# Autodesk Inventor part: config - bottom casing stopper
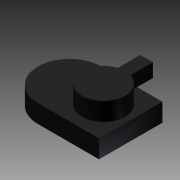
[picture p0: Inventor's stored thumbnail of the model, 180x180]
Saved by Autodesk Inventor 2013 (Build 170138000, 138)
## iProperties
Company: Autodesk Inc.
Created: 2005-12
Part Number: config - bottom casing stopper
Document SubType Name: Modeling
Designer: Autodesk Inc.
Stock Number: config - bottom casing stopper
Density: 1 g/cm^3
Mass: 1.3879 g
Surface Area: 9.59913 cm^2
Volume: 1.3879 cm^3
Material: Allgemein
Title: PC Demo
Author: Autodesk Inc.
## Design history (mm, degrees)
sketch "Sketch1"
  geometry: L1 (0, 12.35)-(0, -7.6) reference; L2 (-6.65, 0)-(6.65, 0) reference; L3 (-1.4, 0)-(1.4, 0); L4 (1.4, 0)-(1.4, 9.5); L5 (1.4, 9.5)-(-1.4, 9.5); L6 (-1.4, 9.5)-(-1.4, 0); C1 r 4.75 at (0, 0)
  constraints: 8 end point, 2 parallel, 2 point on line, 1 centre point, 1 horizontal, 1 midpoint, 1 perpendicular, 1 other
  dimensions: "d0" = 9.5 diameter of C1; "d3" = 9.5 distance of L5.end L3.start; "d4" = 2.8 distance of L4.end L5.end
extrude "Extrusion2" new body sketch "Sketch1" distance "d5" = 4; taper "d6" = 0 deg
extrude "Extrusion3" join sketch "Sketch1" distance "d7" = 3; taper "d8" = 0 deg
sketch "Sketch2"
  geometry: L1 (0, -9.8)-(0, 9.8) reference; L2 (-10.1, 0)-(18.6, 0) reference; L3 (-6, 7)-(7.5, 7); L4 (7.5, 7)-(7.5, -7); L5 (7.5, -7)-(-6, -7); L6 (-6, -7)-(-6, 7); C1 r 4.75 at (0, 0) reference; 1 further point
  constraints: 8 end point, 2 parallel, 1 horizontal, 1 midpoint, 1 perpendicular, 1 vertical alignment, 3 other
  dimensions: "d9" = 7.5 distance between parallel lines of L1 L4; "d10" = 6 distance between parallel lines of L1 L6; "d11" = 14 distance of L5.end L3.start
extrude "Extrusion4" join sketch "Sketch2" distance "d12" = 4; taper "d13" = 0 deg
body "Solid1"
